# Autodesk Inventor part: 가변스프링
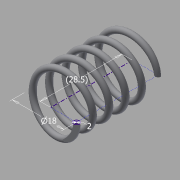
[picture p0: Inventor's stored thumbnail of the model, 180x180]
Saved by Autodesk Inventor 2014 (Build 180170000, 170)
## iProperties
Created: 2018-12
Part Number: 가변스프링
Material: Generic
Document SubType Name: Modeling
Designer: kh
Density: 1 g/cm^3
Appearance: Default
Mass: 0.875199 g
Surface Area: 17.7587 cm^2
Volume: 0.875199 cm^3
Author: kh
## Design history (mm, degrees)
sketch "스케치1"
  geometry: L1 (0, 0)-(9, 0); L2 (9, 0)-(9, 28.5); L3 (9, 28.5)-(0, 28.5); L4 (0, 28.5)-(0, 0); C1 r 1 at (9, 0)
  constraints: 8 end point, 2 parallel, 1 centre point, 1 coincident, 1 horizontal, 1 perpendicular
  dimensions: "d0" = 2 diameter of C1; "d1" = 28.5 distance of L3.end L1.start (derived); "d2" = 18 diameter of L2 L4
feature "코일1" sketch "스케치1" pitch "d3" = 10; turns "d5" = 5; dims "d4" = 28.5 (= d1), "d6" = 0, angle "d7" = 90 deg, angle "d8" = 90 deg, "d9" = 0, "d10" = 0
node "작업 평면1"
node "작업 평면2"
feature "분할1"
feature "분할2"
node "솔리드1"
